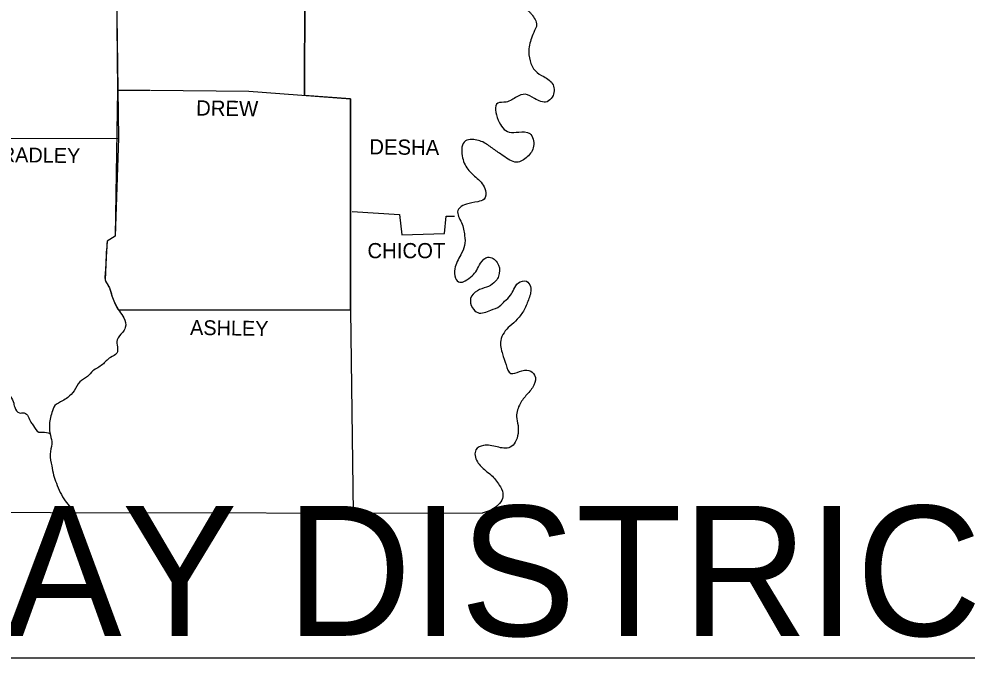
# Model space of a CAD drawing. Extents: x -31696 to 27919, y -8775 to 11152.
# Drawn here: x 13726 to 16350, y 4654 to 6429 of the extents above; entities that cross this region are included whole.
import ezdxf

# ---------------------------------------------------------------- set-up
doc = ezdxf.new("R2010")
doc.units = 0
for name, color, linetype in [('Level 1', 7, 'Continuous'), ('Level 2', 7, 'Continuous'), ('Level 48', 7, 'Continuous')]:
    doc.layers.add(name, color=color, linetype=linetype)

msp = doc.modelspace()

# ---------------------------------------------------------------- linework, layer by layer
at = {"layer": 'Level 1'}
msp.add_line((9156.5, 4659.5), (17226.8, 4659.5), dxfattribs=at)
for points in [[(14015.3, 6628.3), (14016.3, 6506), (13995.8, 6505), (14001.6, 6099)], [(14676.7, 6576.4), (14665, 6550), (14613.1, 6545.1), (14610.2, 6509.9), (14517.3, 6509.9), (14516.3, 6217.4)], [(13998.7, 6232), (14087.9, 6231.3)], [(14090.3, 6231.3), (14361.7, 6229.1), (14643.5, 6207.6)], [(14643.5, 6207.6), (14643.5, 5622.5), (14651.3, 5059.9)], [(13559.4, 6098), (14001.6, 6099)], [(14001.6, 6099), (13991.9, 5827), (13970.3, 5813.3)], [(14648.4, 5895.5), (14779.5, 5887.6), (14785.3, 5830.9), (14903.7, 5834.8), (14908.6, 5882.7), (14931.1, 5882.7)], [(11420.6, 5857.3), (11422.6, 5065.8), (15008.4, 5059.9)], [(14001.1, 5623.5), (14643.5, 5623.5)]]:
    msp.add_lwpolyline(points, dxfattribs=at)
for points in [[(15270.9, 6755.7), (15269.7, 6752.6), (15268.5, 6744.2), (15270, 6735.2), (15273.8, 6726.3), (15279.4, 6718.3), (15288.2, 6713.1), (15298.8, 6711.4), (15309.2, 6709.7), (15317.6, 6704.6), (15323.4, 6697.2), (15328.4, 6689.4), (15335.2, 6672.3), (15336.2, 6642), (15323.5, 6601.9), (15320, 6596), (15316.1, 6590.6), (15305.9, 6583.3), (15271.6, 6575.5), (15268.3, 6574.9), (15258.4, 6573.7), (15251.7, 6572.6), (15248.4, 6571.7), (15245.2, 6570.6), (15241.1, 6567.5), (15239.2, 6563), (15239.7, 6551.1), (15242, 6537.7), (15242.3, 6531.3), (15241.3, 6525.6), (15239.3, 6519.7), (15237.2, 6513.9), (15229.5, 6503.1), (15219.3, 6496.5), (15209, 6496.2), (15201.7, 6499.5), (15194.4, 6503.5), (15187.1, 6507.4), (15179.6, 6510.9), (15162, 6517.7), (15140.5, 6527.5), (15133.5, 6531.3), (15126.6, 6535.7), (15119.9, 6540.2), (15113.1, 6544.2), (15102.6, 6545.7), (15097.2, 6544.3), (15092.6, 6541.2), (15087.4, 6531.5), (15087.7, 6519.7), (15092, 6507.9), (15098.4, 6498.2), (15100.4, 6496.2), (15112.1, 6480), (15123.9, 6463.9), (15135.5, 6451.7), (15141.6, 6445.5), (15147.4, 6438.5), (15156.1, 6423.4), (15158.3, 6415.7), (15158.1, 6408.2)], [(15158.1, 6408.2), (15148.3, 6385.6), (15137.6, 6346.5), (15140.5, 6313.2), (15155.2, 6284.9), (15178.7, 6269.2), (15204.1, 6246.7), (15202.1, 6212.5), (15187.5, 6199.8), (15153.2, 6208.6), (15126.8, 6220.3), (15104.3, 6213.4), (15074, 6198.8), (15051.5, 6195.8), (15052.4, 6148.9), (15082.8, 6115.6), (15109.2, 6115.6), (15139.5, 6111.7), (15150.3, 6076.5), (15132.7, 6047.1), (15103.3, 6032.4), (15066.1, 6050.1), (15039.7, 6068.6), (15013.3, 6086.3), (14980, 6095.1), (14961.5, 6091.1), (14952.7, 6050.1), (14968.3, 6012.9), (14993.7, 5987.4), (15017.2, 5954.2), (15013.3, 5929.7), (14995.7, 5922.9), (14964.4, 5916), (14945.8, 5906.2), (14940.9, 5898.4), (14950.7, 5865.1), (14959.5, 5828.9), (14959.5, 5801.5), (14948.7, 5776.1), (14932.1, 5737), (14934.1, 5711.5), (14945.8, 5699.8), (14960.5, 5703.7), (14980, 5717.4), (14992.8, 5733.1), (15003.5, 5752.6), (15024.1, 5769.3), (15049.5, 5754.6), (15055.4, 5724.2), (15040.7, 5697.8), (15020.2, 5686.1), (14994.7, 5676.3), (14976.1, 5654.8), (14981, 5629.3), (14995.7, 5615.6), (15031.9, 5622.5), (15056.4, 5633.3), (15070.1, 5647), (15086.7, 5663.6), (15095.5, 5680.2), (15108.2, 5697.8), (15130.7, 5702.7), (15141.5, 5688), (15137.6, 5654.8), (15123.9, 5623.5), (15105.3, 5597.1), (15084.7, 5578.5), (15059.3, 5538.3), (15064.2, 5501.2), (15074, 5470.8), (15087.7, 5447.4), (15111.2, 5452.2), (15137.6, 5455.2), (15153.2, 5442.5), (15151.3, 5415.1), (15131.7, 5388.7), (15113.1, 5363.2), (15103.3, 5328), (15107.2, 5303.5), (15107.2, 5281), (15099.4, 5256.6), (15085.7, 5242.9), (15049.5, 5243.8), (15011.4, 5247.8), (14990.8, 5236), (14994.7, 5202.8), (15017.2, 5178.3), (15032.9, 5165.6), (15055.4, 5138.2), (15065.2, 5115.7), (15062.2, 5096.1), (15048.5, 5079.5), (15008.4, 5059.9)], [(13970.3, 5813.3), (13967.4, 5783), (13966.4, 5754.6), (13964.5, 5727.2), (13964.5, 5706.6), (13976.2, 5684.1), (13983.1, 5662.6), (13989.9, 5644), (14003.6, 5619.6), (14016.3, 5601), (14020.2, 5574.5), (14012.4, 5560.9), (13997.7, 5540.3), (13996.7, 5503.1), (13979.1, 5491.4), (13956.6, 5471.8), (13943.9, 5463), (13930.2, 5454.2), (13915.5, 5438.6), (13894, 5423.9), (13878.4, 5399.4), (13860.7, 5380.8), (13846.1, 5371), (13825.5, 5358.3), (13816.7, 5338.8), (13809.9, 5302.6), (13812.8, 5276.1), (13816.7, 5252.7), (13811.8, 5223.3), (13816.7, 5191), (13821.6, 5165.6), (13829.4, 5143.1), (13840.2, 5117.6), (13853.9, 5094.2), (13883.3, 5058)], [(12994.9, 5587.3), (13010.5, 5598), (13025.2, 5603.9), (13039.9, 5601), (13055.5, 5599), (13069.2, 5601), (13086.8, 5598), (13101.5, 5589.2), (13118.1, 5582.4), (13134.8, 5582.4), (13149.4, 5582.4), (13162.2, 5573.6), (13185.6, 5574.5), (13205.2, 5582.4), (13224.8, 5588.2), (13251.2, 5591.2), (13274.7, 5574.5), (13291.3, 5560.9), (13305, 5545.2), (13314.8, 5527.6), (13325.6, 5517.8), (13343.2, 5511), (13356.9, 5508), (13373.5, 5503.1), (13382.3, 5499.2), (13390.1, 5480.6), (13402.9, 5455.2), (13427.3, 5446.4), (13457.6, 5458.1), (13482.1, 5465), (13499.7, 5470.8), (13510.5, 5474.8), (13520.3, 5475.7), (13517.3, 5477.7), (13529.1, 5480.6), (13539.8, 5472.8), (13546.7, 5462), (13558.4, 5446.4), (13569.2, 5432.7), (13579.9, 5427.8), (13590.7, 5433.7), (13605.4, 5428.8), (13618.1, 5423.9), (13632.8, 5420), (13645.5, 5419), (13662.1, 5415.1), (13674.9, 5408.2), (13686.6, 5401.4), (13698.3, 5388.7), (13710.1, 5369.1), (13714, 5353.4), (13727.7, 5337.8), (13740.4, 5337.8), (13759, 5312.3), (13765.8, 5302.6), (13780.5, 5284.9), (13791.3, 5284.9), (13811.8, 5281)]]:
    msp.add_spline(points, degree=3, dxfattribs=at)
at = {"layer": 'Level 48'}
for points in [[(14643.5, 5622.5), (14643.5, 6207.6), (14516.3, 6217.4), (14517.3, 6509.9)], [(14643.5, 5622.5), (14643.5, 6207.6), (14516.3, 6217.4), (14517.3, 6509.9)], [(13995.8, 6505), (13998.7, 6232), (13991.9, 5827), (13970.3, 5813.3), (13966.9, 5768.8), (13964.5, 5706.6), (13970.3, 5695.4), (13976.2, 5684.1), (13983.1, 5662.6), (13989.9, 5644), (13996.7, 5631.8), (14001.1, 5623.5), (14322.3, 5623.5), (14643.5, 5623.5)], [(13995.8, 6505), (13998.7, 6232), (13991.9, 5827), (13970.3, 5813.3), (13966.9, 5768.8), (13964.5, 5706.6), (13970.3, 5695.4), (13976.2, 5684.1), (13983.1, 5662.6), (13989.9, 5644), (13996.7, 5631.8), (14001.1, 5623.5), (14322.3, 5623.5), (14643.5, 5622.5)]]:
    msp.add_lwpolyline(points, dxfattribs=at)

# ---------------------------------------------------------------- texts
at = {"layer": 'Level 2'}
for s, height, rotation, p in [('DREW', 42.06, 359.2258, (14215.9, 6161.6)), ('DESHA', 42.06, 359.3704, (14695.3, 6054)), ('BRADLEY', 41.08, 359.1449, (13638.7, 6033.4)), ('ASHLEY', 41.09, 359.2361, (14199.3, 5554))]:
    msp.add_text(s, height=height, rotation=rotation, dxfattribs=at).set_placement(p)
for s, height, p in [('CHICOT', 42.07, (14690.4, 5766.3)), ('ARKANSAS HIGHWAY DISTRICTS 1, 2 & 6', 360, (9275.5, 4720.5))]:
    msp.add_text(s, height=height, dxfattribs=at).set_placement(p)

doc.saveas('drawing.dxf')
